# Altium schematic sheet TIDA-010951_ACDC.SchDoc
size 431 x 279 mm; Date: Not shown in title block; ApprovedBy: Not shown in title block; CheckedBy: Not shown in title block; Author: Not shown in title block; CompanyName: Not shown in title block; DrawnBy: Jenson Fang; Engineer: Not shown in title block; Organization: Not shown in title block; Address1: Not shown in title block; Address2: Not shown in title block; Address3: Not shown in title block; Address4: Not shown in title block; DocumentNumber: 1; Revision: Use project parameter SCH_Rev; SheetNumber: 1; SheetTotal: 2; PageSetup: Record=PageOptions¦CenterHorizontal=True¦CenterVertical=True¦PrintScale=1.00¦XCorrection=1.00¦YCorrection=1.00¦PrintKind=0¦BorderSize=5000000¦LeftOffset=0¦BottomOffset=0¦Orientation=2¦PaperLength=1000¦PaperWidth=1000¦Scale=100¦PaperSource=15¦PrintQuality=600¦MediaType=1¦DitherType=10¦PaperKind=Letter¦PrintScaleMode=1
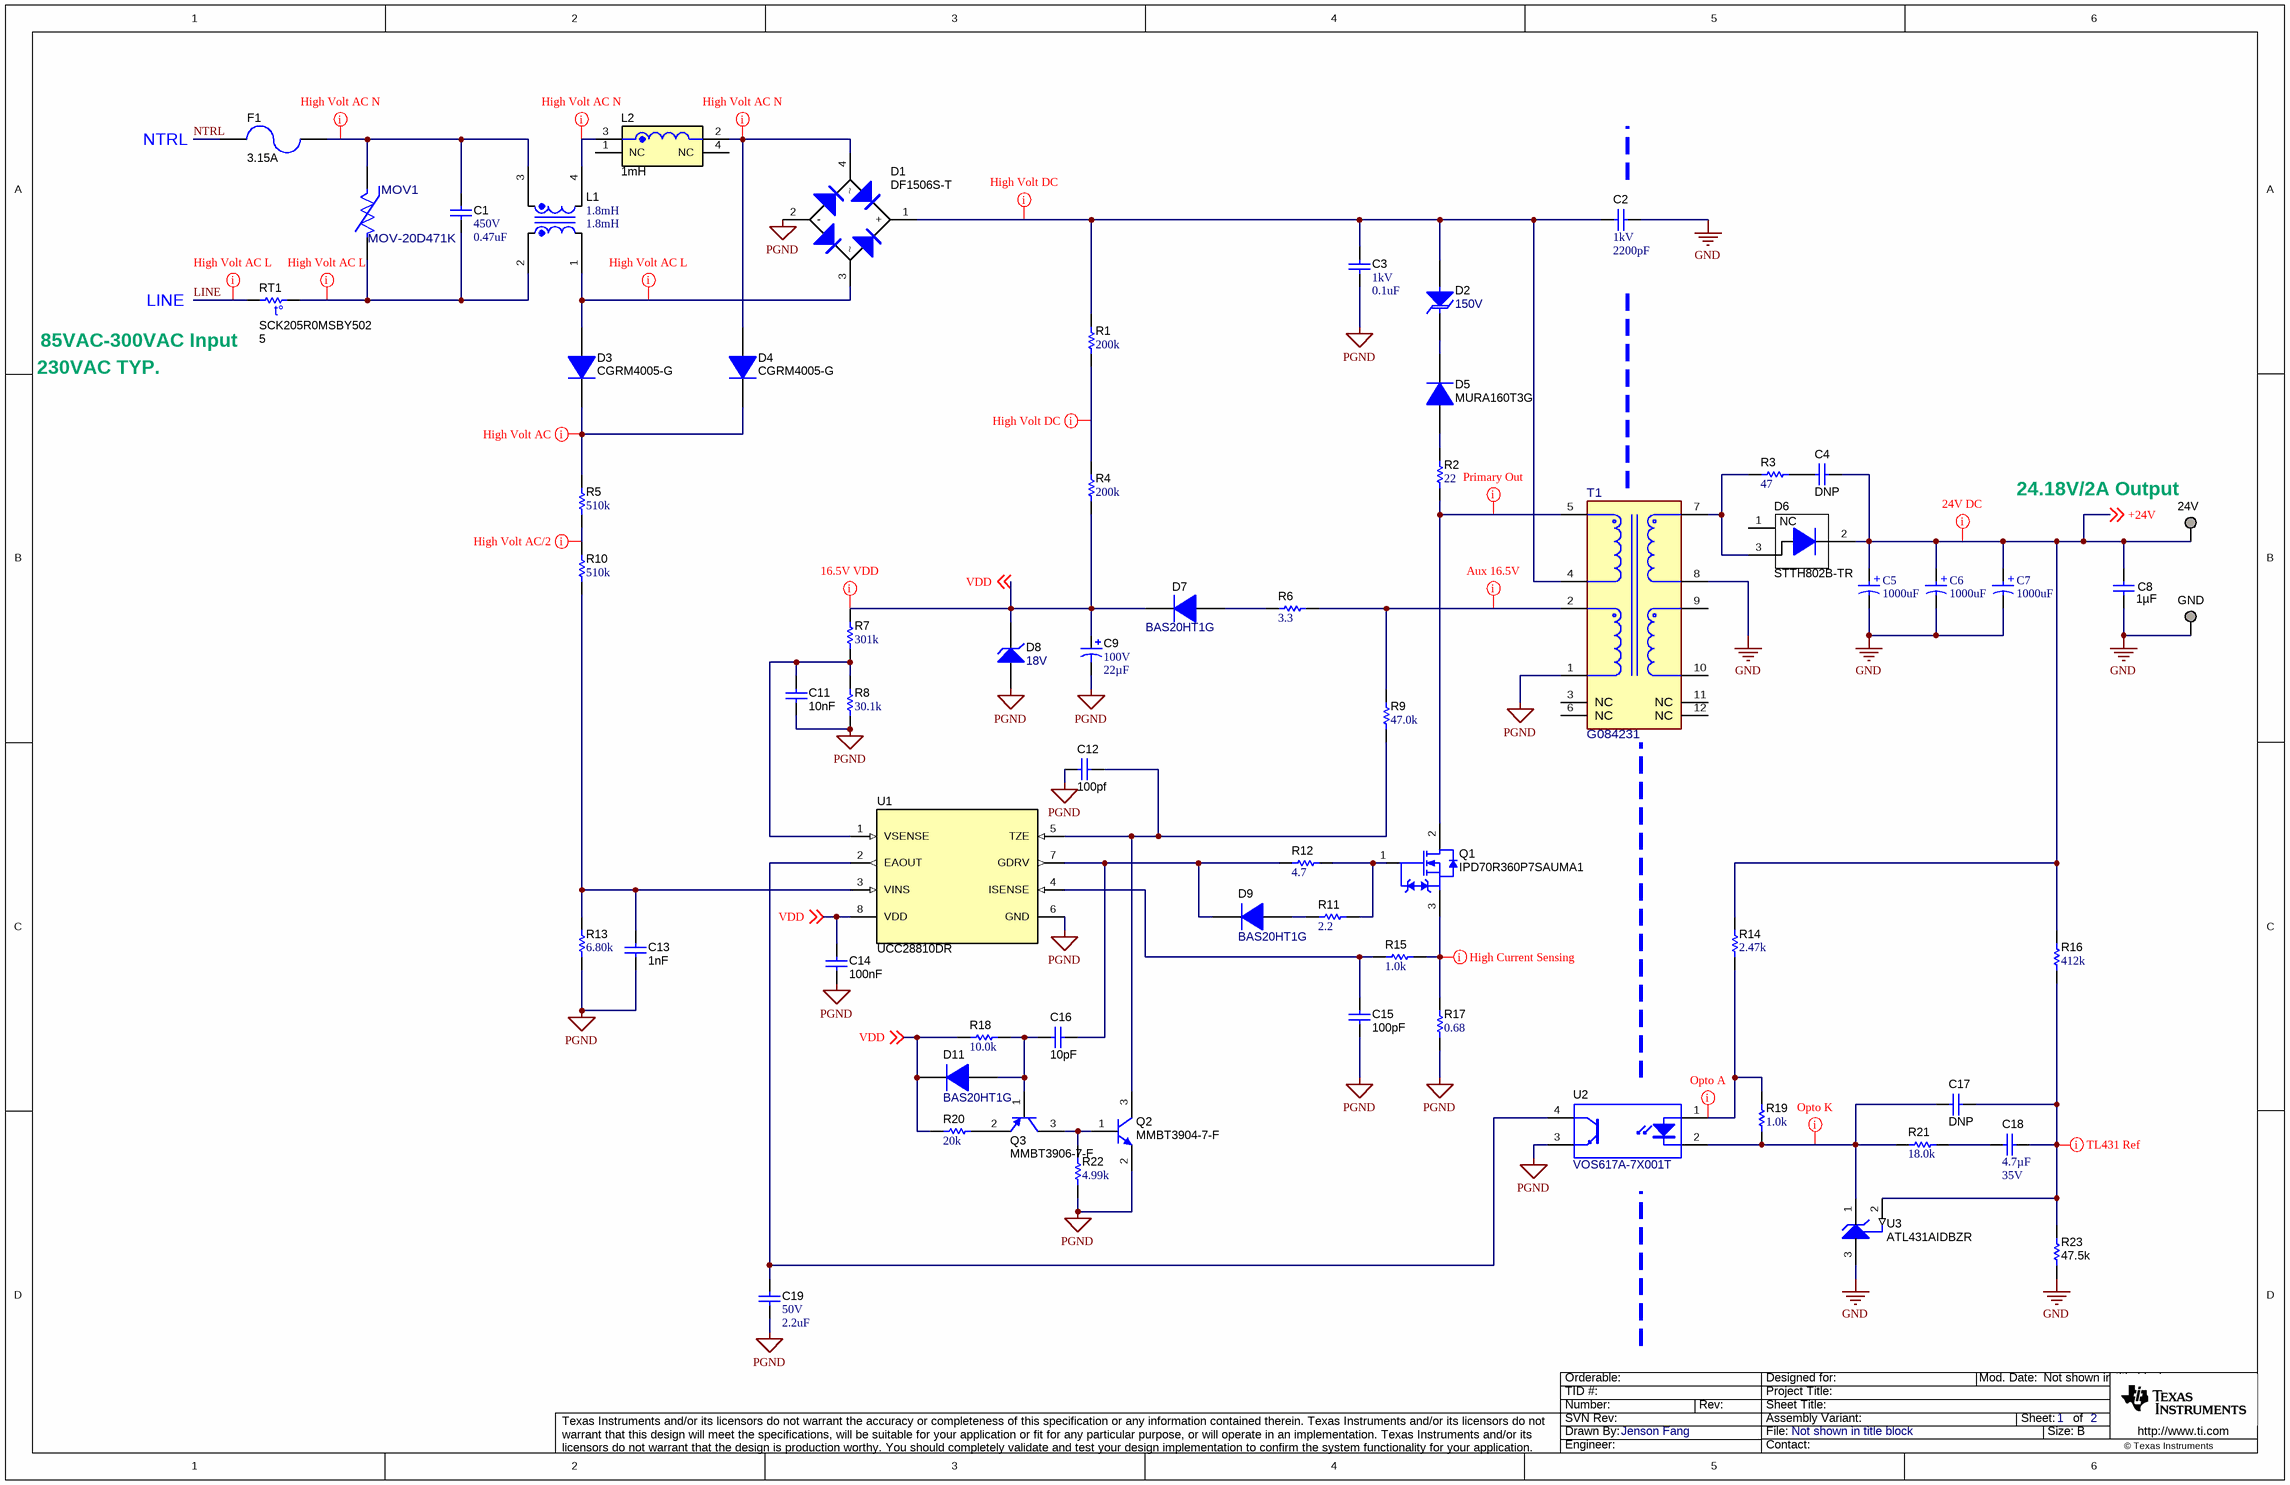
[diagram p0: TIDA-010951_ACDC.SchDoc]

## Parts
24V  TP_H0.45P0.75  [TP_H045P075]  (value not drawn)  (no BOM)
C1  VDC_V: 450V  ValueDisplayed: 0.47uF  [MPK_1800x650]  (hidden comment: 450MPK474J)
C2  VDC_V: 1kV  ValueDisplayed: 2200pF  [1206]  (hidden comment: GRM31BR73A222KW01L)
C3  VDC_V: 1kV  ValueDisplayed: 0.1uF  [2220]  (hidden comment: GRM55DR73A104KW01L)
C4  DNP  [0805_HV]
C5  1000uF  [WCAP-ATLL_D10H30]
C6  1000uF  [WCAP-ATLL_D10H30]
C7  1000uF  [WCAP-ATLL_D10H30]
C8  Cap_F: 1µF  [0603]  (hidden comment: UMK107AB7105KA-T)
C9  VDC_V: 100V  ValueDisplayed: 22µF  [VR_630X1100]  (hidden comment: UVR2A220MED1TD)
C11  Cap_F: 10nF  [0603]  (hidden comment: C1608X7R1H103K080AA)
C12  ValueDisplayed: 100pf  [0603]  (hidden comment: GRM1885C1H100JA01D)
C13  Cap_F: 1nF  [0603]  (hidden comment: C0603X102K5RACTU)
C14  Cap_F: 100nF  [0603]  (hidden comment: GRM188R71H104KA93D)
C15  ValueDisplayed: 100pF  [0603]  (hidden comment: C1608C0G1H101J080AE)
C16  ValueDisplayed: 10pF  [0603]  (hidden comment: GRM1885C1H100JA01D)
C17  ValueDisplayed: DNP  [0603]  (hidden comment: C1608X5R1V225K080AC)
C18  Cap_F: 4.7µF  VDC_V: 35V  [0805_HV]  (hidden comment: C2012X7R1V475K125AC)
C19  VDC_V: 50V  ValueDisplayed: 2.2uF  [0805_HV]  (hidden comment: C2012X6S1H225K125AB)
D1  DF1506S-T  [DF-S]
D2  value 150V  [SMC]  (hidden comment: SMCJ150A-TP)
D3  CGRM4005-G  [MINI-SMA]
D4  CGRM4005-G  [MINI-SMA]
D5  MURA160T3G  [SMA]
D6  STTH802B-TR  [DPAK]
D7  BAS20HT1G  [SOD-323]
D8  value 18V  [SOD-123]  (hidden comment: MMSZ4705-E3-08)
D9  BAS20HT1G  [SOD-323]
D11  BAS20HT1G  [SOD-323]
F1  value 3.15A  [FUSE_392]  (hidden comment: 39213150000)
GND  TP_H0.45P0.75  [TP_H045P075]  (value not drawn)  (no BOM)
L1  value 1.8mH  [WE-TFCH_UT]  (hidden comment: 744861018)
L2  value 1mH  [WE-TIF_1018]  (hidden comment: 7447231102)
MOV1  MOV-20D471K  [FP-MOV-20D471K_RADIAL-MFG]
Q1  IPD70R360P7SAUMA1  [DPAK]
Q2  MMBT3904-7-F  [SOT-23]
Q3  MMBT3906-7-F  [SOT-23]
R1  ValueDisplayed: 200k  [1210]  (hidden comment: RC1210JR-07200KL)
R2  ValueDisplayed: 22  [2512]  (hidden comment: CRCW251222R0JNEGHP)
R3  ValueDisplayed: 47  [1206]  (hidden comment: CRCW120647R0JNEA)
R4  ValueDisplayed: 200k  [1210]  (hidden comment: RC1210JR-07200KL)
R5  ValueDisplayed: 510k  [1206]  (hidden comment: RC1206FR-07510KL)
R6  ValueDisplayed: 3.3  [0805_HV]  (hidden comment: RC0805JR-073R3L)
R7  ValueDisplayed: 301k  [0603]  (hidden comment: RC0603FR-07301KL)
R8  ValueDisplayed: 30.1k  [0603]  (hidden comment: RC0603FR-0730K1L)
R9  ValueDisplayed: 47.0k  [0603]  (hidden comment: RC0603FR-0747KL)
R10  ValueDisplayed: 510k  [1206]  (hidden comment: RC1206FR-07510KL)
R11  ValueDisplayed: 2.2  [0805_HV]  (hidden comment: RC0805JR-072R2L)
R12  ValueDisplayed: 4.7  [0805_HV]  (hidden comment: RPC0805JT4R70)
R13  ValueDisplayed: 6.80k  [0603]  (hidden comment: RC0603FR-076K8L)
R14  ValueDisplayed: 2.47k  [0603]  (hidden comment: CR0603-JW-472GLF)
R15  ValueDisplayed: 1.0k  [0603]  (hidden comment: RC0603JR-071KL)
R16  ValueDisplayed: 412k  [0603]  (hidden comment: RC0603FR-07412KL)
R17  ValueDisplayed: 0.68  [2512]  (hidden comment: ERJ-1TRQJR68U)
R18  ValueDisplayed: 10.0k  [0402]  (hidden comment: ERJ-2RKF1002X)
R19  ValueDisplayed: 1.0k  [0603]  (hidden comment: RC0603JR-071KL)
R20  ValueDisplayed: 20k  [0402]  (hidden comment: ERJ-2GEJ203X)
R21  ValueDisplayed: 18.0k  [0603]  (hidden comment: RC0603FR-0718KL)
R22  ValueDisplayed: 4.99k  [0402]  (hidden comment: RC0402FR-074K99L)
R23  ValueDisplayed: 47.5k  [0603]  (hidden comment: RC0603FR-0747K5L)
RT1  SCK205R0MSBY502  value 5  [SCK20_S]
T1  G084231  [FP-G084231_PTH_TRANSFORMER_31MM50_24MM50-MFG]
U1  UCC28810DR  [D0008A_N]
U2  VOS617A-7X001T  [SSOP-4_VISHAY]
U3  ATL431AIDBZR  [DBZ0003A_N]

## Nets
GND: C2.1 C5.2(N) C6.2(N) C7.2(N) C8.2 GND.1 R23.1 T1.8 U3.3(ANODE)
PGND: C3.2 C9.2(-) C11.2 C12.1 C13.2 C14.2 C15.2 C19.2 D1.2(-) D8.2(A) Q2.2(E) R8.1 R13.1 R17.1 R22.1 T1.1 U1.6(GND) U2.3(E)
+24V: 24V.1 C4.2 C5.1(P) C6.1(P) C7.1(P) C8.1 D6.2(K) R14.2 R16.2 ; off-sheet +24V
LINE: RT1.1
NTRL: F1.2
VDD: C9.1(+) C14.1 D7.1(K) D8.1(K) D11.1(K) R4.1 R7.2 R18.1 R20.1 U1.8(VDD) ; off-sheet VDD
NetC1_1: C1.1 F1.1 L1.3 MOV1.2
NetC1_2: C1.2 L1.2 MOV1.1 RT1.2
NetC2_2: C2.2 C3.1 D1.1(+) D2.2(A) R1.2 T1.4
NetC4_1: C4.1 R3.2
NetC11_1: C11.1 R7.1 R8.2 U1.1(VSENSE)
NetC12_2: C12.2 Q2.3(C) R9.1 U1.5(TZE)
NetC13_1: C13.1 R10.1 R13.2 U1.3(VINS)
NetC15_1: C15.1 R15.2 U1.4(ISENSE)
NetC16_1: C16.1 D11.2(A) Q3.1(B) R18.2
NetC16_2: C16.2 D9.1(K) R12.1 U1.7(GDRV)
NetC17_1: C17.1 R19.1 R21.1 U2.2(K) U3.1(CATHODE)
NetC17_2: C17.2 C18.1 R16.1 R23.2 U3.2(REF)
NetC18_2: C18.2 R21.2
NetC19_1: C19.1 U1.2(EAOUT) U2.4(C)
NetD1_3: D1.3 D3.2(A) L1.1
NetD1_4: D1.4 D4.2(A) L2.2
NetD2_1: D2.1(K) D5.1(K)
NetD3_1: D3.1(K) D4.1(K) R5.2
NetD5_2: D5.2(A) R2.2
NetD6_3: D6.3(A) R3.1 T1.7
NetD7_2: D7.2(A) R6.1
NetD9_2: D9.2(A) R11.1
NetL1_4: L1.4 L2.3
NetQ1_1: Q1.1(G) R11.2 R12.2
NetQ1_2: Q1.2(D) R2.1 T1.5
NetQ1_3: Q1.3(S) R15.1 R17.2
NetQ2_1: Q2.1(B) Q3.3(C) R22.2
NetQ3_2: Q3.2(E) R20.2
NetR1_1: R1.1 R4.2
NetR5_1: R5.1 R10.2
NetR6_2: R6.2 R9.2 T1.2
NetR14_1: R14.1 R19.2 U2.1(A)

Not connected (* = marked no-connect by the designer): D6 1(NC); L2 1(NC) 4(NC); T1 3(NC) 6(NC) 9 10 11(NC) 12(NC)

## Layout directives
net class High Volt AC N: NetC1_1, NetD1_4, NetL1_4
net class High Volt AC L: LINE, NetC1_2, NetD1_3
net class High Volt DC: NetC2_2, NetR1_1
net class 18V VDD: VDD
net class Aux 16.5V: NetR6_2
net class Primary Out: NetQ1_2
net class 24V DC: +24V
net class TL431 Ref: NetC17_2
net class Opto K: NetC17_1
net class Opto A: NetR14_1
net class High Current Sensing: NetQ1_3
net class High Volt AC/2: NetR5_1
net class High Volt AC: NetD3_1

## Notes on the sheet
- NTRL
- LINE
- 230VAC TYP.
- (near RT1) 85VAC-300VAC Input
- (near 24V) 24.18V/2A Output

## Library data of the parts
24V GND = CMP-0003719-1: Testpoint; Manufacturer: Texas Instruments; CompType: Pad
C1 = CMP-0012309-3: CAP, Film, 0.47 uF, 450 V, +/- 5%, TH; Manufacturer: Rubycon; TaMin_C: -40°C; Polarized: N; Value1: Unknown; Value: 0.47uF; TaMax_C: 105°C; Cap_Case: 18x6.5mm; Cap_F: 470nF; AEC Category: Q200
C2 = CMP-0008918-2: CAP, CERM, 2200 pF, 1000 V, +/- 10%, X7R, 1206; Manufacturer: MuRata; TaMin_C: -55°C; Polarized: N; SizeAreaWB_mm2: 10.92; Value1: Unknown; U/M: EA; Value: 2200pF; TaMax_C: 125°C; SizeZ_mm: 1.35; SizeX_mm: 3.2; SizeY_mm: 1.6; Value2: 1000V; SizeArea_mm2: 5.12; Cap_F: 2.2nF; AEC Category: Q200
C3 = CMP-0009470-2: CAP, CERM, 0.1 uF, 1000 V, +/- 10%, X7R, 2220; Manufacturer: MuRata; TaMin_C: -55°C; Polarized: N; SizeAreaWB_mm2: 53.9; Value1: Unknown; U/M: EA; Value: 0.1uF; TaMax_C: 125°C; SizeZ_mm: 1.35; SizeX_mm: 5.7; SizeY_mm: 5; Value2: 1000V; SizeArea_mm2: 28.5; Cap_F: 100nF; AEC Category: Q200
C4 = CMP-0008310-1: TaMin_C: -55°C; Polarized: N; TempCo: X5R; SizeAreaWB_mm2: 6.75; Value1: Unknown; U/M: EA; TaMax_C: 85°C; Tolerance_%: 10%; SizeZ_mm: 1.45; SizeX_mm: 2; SizeY_mm: 1.25; Cap_Case: 0805; Value2: 250V; SizeArea_mm2: 2.5; AEC Category: Q200
C5 = CMP-03913-55434168-1: 860160575031 WCAP-ATLL Aluminum Electrolytic Capacitors 35VDC; Voltage Rating: 35V; Tolerance: 20%; Leakage Current: 350µA; Pitch: 5mm; Life (Hours): 6000hours; Impedance: 60mΩ; Capacitance: 1mF; Polarity: Polar; Material: Aluminium; Ripple Current: 2.136A
C6 C7 = CMP-03913-55434168-1: 860160575031 WCAP-ATLL Aluminum Electrolytic Capacitors; Voltage Rating: 35V; Tolerance: 20%; Leakage Current: 350µA; Pitch: 5mm; Life (Hours): 6000hours; Impedance: 60mΩ; Capacitance: 1mF; Polarity: Polar; Material: Aluminium; Ripple Current: 2.136A
C8 = CMP-0007508-5: CAP, CERM, 1 uF, 50 V, +/- 10%, X7R, 0603; Manufacturer: Taiyo Yuden; TaMin_C: -55°C; Polarized: N; SizeAreaWB_mm2: 4.68; Value1: Unknown; U/M: EA; Value: 1uF; TaMax_C: 125°C; SizeZ_mm: 1; SizeX_mm: 1.6; SizeY_mm: 0.8; Value2: 50V; SizeArea_mm2: 1.28; AEC Category: Q200
C9 = CMP-0860355-1: CAP, AL, 22 µF, 100 V, +/- 20%, TH; Manufacturer: Nichicon; TaMin_C: -40°C; SizeAreaWB_mm2: 68.89; AEC Category: Q200; AEC Qualified: N; U/M: EA; Cap_Case: 6.3x11mm; TaMax_C: 85°C; Value: 22uF; SizeY_mm: 6.3; CompType: Capacitor; Polarized: Y; SizeZ_mm: 12.5; SizeArea_mm2: 39.69
C11 = CMP-0007043-2: CAP, CERM, 0.01 uF, 50 V, +/- 10%, X7R, 0603; Manufacturer: TDK; TaMin_C: -55°C; ESR_ohm: 53.9m; Polarized: N; SizeAreaWB_mm2: 4.68; Value1: 0.0539 ohm; U/M: EA; Value: 0.01uF; TaMax_C: 125°C; SizeZ_mm: 1; SizeX_mm: 1.6; SizeY_mm: 0.8; Value2: 50V; SizeArea_mm2: 1.28; AEC Category: Q200
C12 C16 = CMP-0007170-4: CAP, CERM, 10 pF, 50 V, +/- 5%, C0G/NP0, 0603; Manufacturer: MuRata; TaMin_C: -55°C; Polarized: N; SizeAreaWB_mm2: 4.68; Value1: Unknown; U/M: EA; Value: 10pF; TaMax_C: 125°C; SizeZ_mm: 1; SizeX_mm: 1.6; SizeY_mm: 0.8; Value2: 50V; SizeArea_mm2: 1.28; AEC Category: Q200
C13 = CMP-0006976-5: CAP, CERM, 1000 pF, 50 V, +/- 10%, X7R, 0603; Manufacturer: Kemet; TaMin_C: -55°C; Polarized: N; SizeAreaWB_mm2: 4.68; Value1: Unknown; U/M: EA; Value: 1000pF; TaMax_C: 125°C; SizeZ_mm: 1; SizeX_mm: 1.6; SizeY_mm: 0.8; Value2: 50V; SizeArea_mm2: 1.28; AEC Category: Q200
C14 = CMP-0007434-4: CAP, CERM, 0.1 uF, 50 V, +/- 10%, X7R, 0603; Manufacturer: MuRata; TaMin_C: -55°C; Polarized: N; SizeAreaWB_mm2: 4.68; Value1: Unknown; U/M: EA; Value: 0.1uF; TaMax_C: 125°C; SizeZ_mm: 1; SizeX_mm: 1.6; SizeY_mm: 0.8; Value2: 50V; SizeArea_mm2: 1.28; AEC Category: Q200
C15 = CMP-0006989-1: CAP, CERM, 100 pF, 50 V, +/- 5%, C0G/NP0, 0603; Manufacturer: TDK; TaMin_C: -55°C; Polarized: N; SizeAreaWB_mm2: 4.68; Value1: Unknown; U/M: EA; Value: 100pF; TaMax_C: 125°C; SizeZ_mm: 1; SizeX_mm: 1.6; SizeY_mm: 0.8; Value2: 50V; SizeArea_mm2: 1.28; AEC Category: Q200
C17 = CMP-0007020-3: CAP, CERM, 2.2 uF, 35 V, +/- 10%, X5R, 0603; Manufacturer: TDK; TaMin_C: -55°C; ESR_ohm: 7.674m; Polarized: N; SizeAreaWB_mm2: 4.68; Value1: 0.007674 ohm; U/M: EA; Value: 2.2uF; TaMax_C: 85°C; SizeZ_mm: 1; SizeX_mm: 1.6; SizeY_mm: 0.8; Value2: 35V; SizeArea_mm2: 1.28; Cap_F: 2.2µF; IRMS_A: 1.8782A; AEC Category: Q200
C18 = CMP-0007885-2: CAP, CERM, 4.7 uF, 35 V, +/- 10%, X7R, 0805; Manufacturer: TDK; TaMin_C: -55°C; ESR_ohm: 2.346m; Polarized: N; SizeAreaWB_mm2: 6.75; Value1: 0.002346 ohm; U/M: EA; Value: 4.7uF; TaMax_C: 125°C; SizeZ_mm: 1.45; SizeX_mm: 2; SizeY_mm: 1.25; Cap_Case: 0805; SizeArea_mm2: 2.5; IRMS_A: 4.2602A; AEC Category: Q200
C19 = CMP-0007857-1: CAP, CERM, 2.2 uF, 50 V, +/- 10%, X6S, 0805; Manufacturer: TDK; TaMin_C: -55°C; ESR_ohm: 3.66m; Polarized: N; SizeAreaWB_mm2: 6.75; Value1: 0.00366 ohm; U/M: EA; Value: 2.2uF; TaMax_C: 105°C; SizeZ_mm: 1.45; SizeX_mm: 2; SizeY_mm: 1.25; Cap_Case: 0805; SizeArea_mm2: 2.5; Cap_F: 2.2µF; IRMS_A: 3.4121A; AEC Category: Q200
D1 = CMP-0029209-3: Diode, Switching-Bridge, 600 V, 1.5 A, DF-S; Manufacturer: Diodes Inc.; SizeAreaWB_mm2: 98.794; Value: 600V; SizeX_mm: 7.4; TJmax_C: 150°C; AEC Category: Q101; Value2: 1.1V; Green_REACh: Incomplete; Green_Lifecycle: Not Set; SizeArea_mm2: 62.974; SizeY_mm: 8.51; Value1: 1.5A; SizeZ_mm: 3.4
D2 = CMP-0005708-3: Diode, TVS, Uni, 150 V, 243 Vc, SMC; Manufacturer: Micro Commercial Components; SizeX_mm: 8.13; Vc: 243V; AEC Category: Q101; SizeY_mm: 6.22; SizeAreaWB_mm2: 83.2686; SizeZ_mm: 2.6; Ppk: 1.5kW; AEC Qualified: N; Ipp: 6.2A; Value1: 1500W; Vbr_Max: 185V; SizeArea_mm2: 50.5686; Vbr_Min: 167V
D3 D4 = CMP-0076945-2: Diode, P-N, 600 V, 1 A, MINI-SMA; Manufacturer: Comchip Technology; Green_Lifecycle: Not Set; Vr_V: 600V; Vf_V: 1.1V; SizeZ_mm: 1.7; SizeX_mm: 3.7; Value: 600V; SizeAreaWB_mm2: 12.22; AEC Qualified: N; SizeArea_mm2: 5.92; Io_A: 1A; TJmax_C: 150°C; AEC Category: Q101; SizeY_mm: 1.6; Green_REACh: Incomplete
D5 = CMP-0029033-2: Diode, Ultrafast, 600 V, 1 A, AEC-Q101, SMA; Manufacturer: ON Semiconductor; AEC Category: Q101; SizeX_mm: 5.59; Io_A: 1A; Green_Lifecycle: Active; Value2: 1.05V; SizeArea_mm2: 16.3228; SizeZ_mm: 2.87; TJmax_C: 175°C; Value: 600V; AEC Qualified: Y; SizeAreaWB_mm2: 37.3428; SizeY_mm: 2.92; Green_REACh: Passed
D6 = CMP-0079155-3: Diode, Ultrafast, 200 V, 8 A, DPAK; Manufacturer: STMicroelectronics; Vf_V: 1.05V; AEC Qualified: N; Value1: 8A; Value: 200V; SizeY_mm: 6.54; SizeAreaWB_mm2: 101.7114; SizeArea_mm2: 64.8114; SizeX_mm: 9.91; TJmax_C: 175°C; RJC_CperW: 3.2; SizeZ_mm: 2.29; AEC Category: Q101
D7 D9 D11 = CMP-0029150-1: Diode, Switching, 200 V, 0.2 A, AEC-Q101, SOD-323; Manufacturer: ON Semiconductor; Io_A: 200mA; Green_Lifecycle: Not Set; SizeAreaWB_mm2: 8.695; Vr_V: 200V; Green_REACh: Incomplete; Value1: 0.2A; TJmax_C: 150°C; U/M: EA; SizeZ_mm: 1; SizeX_mm: 2.7; SizeY_mm: 1.35; Vf_V: 1.25V; SizeArea_mm2: 3.645; AEC Qualified: Y; AEC Category: Q101
D8 = CMP-0077615-3: Diode, Zener, 18 V, 500 mW, SOD-123; Manufacturer: Vishay-Semiconductor; AEC Qualified: N; AEC Category: Q101; SizeX_mm: 3.85; SizeY_mm: 1.7; SizeZ_mm: 1.35; Value1: 0.5W; SizeArea_mm2: 6.545; SizeAreaWB_mm2: 13.095; Power_W: 500mW; RJA_CperW: 340
F1 = CMP-0003561-2: Fuse, 3.15 A, 250VAC/VDC, TH; Manufacturer: Littelfuse; VAC_V: 250V
L1 = CMP-0076855-1: Coupled inductor, 1.8 mH, 1 A, 0.31 ohm, TH; Manufacturer: Wurth Elektronik; AEC Category: Q200; DCR_ohm: 3.1d
L2 = CMP-0079596-1: Inductor, Wirewound, 1 mH, 0.8 A, 0.75 ohm, TH; Manufacturer: Wurth Elektronik; SizeAreaWB_mm2: 169; Irms: 0.8A @ 40C rise; SizeArea_mm2: 121; AEC Qualified: N; AEC Category: Q200; SizeZ_mm: 19; Imax_A: 1A; SizeY_mm: 11; Value2: 0.8A; Isat: 1A @ 10% inductance drop; DCR_ohm: 8.5
MOV1 = CMP-0092775-1: 470 V 6.5 kA Varistor 1 Circuit Through Hole Disc 20mm; Manufacturer: Bourns Inc.; ValueDisplayed: 1020pF; AEC Qualified: No; Clamping Voltage: 775V; Vc: 100A; SizeZ_mm: 26mm; Varistor Voltage: 423V; Voltage Tolerance: 10%; VDC_V: 385V
Q1 = CMP-0081521-2: MOSFET, N-CH, 700 V, 12.5 A, DPAK; Alternate Manufacturer: None; Manufacturer: Infineon Technologies; ChType: N; Value1: ? ohm; ChMode: Enhancement; Value: 700V; SizeArea_mm2: 64.8114; IdsMax_A: 12.5A; Value2: 16.4 nC; SizeX_mm: 9.91; QgTyp_nC: 16.4; AEC Category: Q101; Vgs_V: 16V; SizeZ_mm: 2.29; SizeAreaWB_mm2: 101.7114; SizeY_mm: 6.54
Q2 = CMP-0000387-2: Transistor, NPN, 40 V, 0.2 A, SOT-23; Manufacturer: Diodes Inc.; TaMax_C: 150°C; Value2: 400; Value1: 0.2 A; Vcesat1_V: 2dV; SizeX_mm: 2.5; SizeY_mm: 3; TaMin_C: -55°C; IcRated_A: 2dA; CompType: BJT; SizeZ_mm: 1.1; Value: 40 V; SizeArea_mm2: 7.5; NPN: 1; Vceo_V: 40V; PNP: 0; AEC Category: Q101; SizeAreaWB_mm2: 14; U/M: EA
Q3 = CMP-0000326-2: Transistor, PNP, 40 V, 0.2 A, SOT-23; Manufacturer: Diodes Inc.; TaMax_C: 150°C; Value2: 400; Value1: 0.2 A; Vcesat1_V: 2.5dV; SizeX_mm: 2.5; SizeY_mm: 3; TaMin_C: -55°C; IcRated_A: 2dA; CompType: BJT; SizeZ_mm: 1.1; Value: 40 V; SizeArea_mm2: 7.5; NPN: 0; Vceo_V: 40V; PNP: 1; AEC Category: Q101; SizeAreaWB_mm2: 14; U/M: EA
R1 R4 = CMP-0083494-1: RES, 200 k, 5%, 0.5 W, 1210; Manufacturer: Yageo; Power_W: 500mW; TempCo: 100 ppm/C; SizeAreaWB_mm2: 14.7; Value: 200k; EIA_Code: E24; SizeX_mm: 3.2; SizeY_mm: 2.5; SizeZ_mm: 1.35; Value2: 0.5W; SizeArea_mm2: 8; AEC Qualified: N; VDC_V: 200V; AEC Category: Q200
R2 = CMP-0015919-3: RES, 22, 5%, 1.5 W, AEC-Q200 Grade 0, 2512; Manufacturer: Vishay-Dale; Power_W: 1.5W; TempCo: 200 ppm/C; Value_Code: 22R0; Value: 22; EIA_Code: E24; SizeX_mm: 6.3; SizeY_mm: 3.2; SizeZ_mm: 0.71; SizeArea_mm2: 20.16; AEC Qualified: Y; VDC_V: 500V; AEC Category: Q200; AEC Grade: 0
R3 = CMP-0018687-3: RES, 47, 5%, 0.25 W, AEC-Q200 Grade 0, 1206; Manufacturer: Vishay-Dale; Power_W: 250mW; TempCo: 200 ppm/C; Value_Code: 47R0; Value: 47; EIA_Code: E24; SizeX_mm: 3.2; SizeY_mm: 1.6; SizeZ_mm: 1.35; Value2: 0.25W; SizeArea_mm2: 5.12; AEC Qualified: Y; VDC_V: 200V; AEC Category: Q200; AEC Grade: 0
R5 R10 = CMP-0018353-2: RES, 510 k, 1%, 0.25 W, 1206; Manufacturer: Yageo America; Power_W: 250mW; TempCo: 100 ppm/C; U/M: EA; Value: 510k; SizeX_mm: 3.2; SizeY_mm: 1.6; SizeZ_mm: 1.35; Value2: 0.25W; SizeArea_mm2: 5.12; VDC_V: 200V; AEC Category: Q200
R6 = CMP-0020817-2: RES, 3.3, 5%, 0.125 W, 0805; Manufacturer: Yageo America; Power_W: 125mW; TempCo: 200 ppm/C; Value_Code: 3R30; U/M: EA; Value: 3.3; EIA_Code: E24; SizeX_mm: 2; SizeY_mm: 1.25; SizeZ_mm: 1.45; Value2: 0.125W; SizeArea_mm2: 2.5; VDC_V: 150V; AEC Category: Q200
R7 = CMP-0023014-4: RES, 301 k, 1%, 0.1 W, 0603; Manufacturer: Yageo; Power_W: 100mW; TempCo: 100 ppm/C; Value: 301k; EIA_Code: E96; SizeX_mm: 1.6; SizeY_mm: 0.8; SizeZ_mm: 1; Value2: 0.1W; SizeArea_mm2: 1.28; AEC Qualified: N; VDC_V: 75V; AEC Category: Q200; SizeAreaWB_mm2: 4.68
R8 = CMP-0023018-5: RES, 30.1 k, 1%, 0.1 W, 0603; Manufacturer: Yageo; Power_W: 100mW; TempCo: 100 ppm/C; Value_Code: 30k1; Value: 30.1k; EIA_Code: E96; SizeX_mm: 1.6; SizeY_mm: 0.8; SizeZ_mm: 1; Value2: 0.1W; SizeArea_mm2: 1.28; AEC Qualified: N; VDC_V: 75V; AEC Category: Q200; SizeAreaWB_mm2: 4.68
R9 = CMP-0023133-5: RES, 47.0 k, 1%, 0.1 W, 0603; Manufacturer: Yageo; Power_W: 100mW; TempCo: 100 ppm/C; Value_Code: 47k0; Value: 47.0k; Res_ohm: 47k; SizeX_mm: 1.6; SizeY_mm: 0.8; SizeZ_mm: 1; Value2: 0.1W; SizeArea_mm2: 1.28; AEC Qualified: N; VDC_V: 75V; AEC Category: Q200; SizeAreaWB_mm2: 4.68
R11 = CMP-0020812-2: RES, 2.2, 5%, 0.125 W, 0805; Manufacturer: Yageo America; Power_W: 125mW; TempCo: 200 ppm/C; Value_Code: 2R20; U/M: EA; Value: 2.2; EIA_Code: E24; SizeX_mm: 2; SizeY_mm: 1.25; SizeZ_mm: 1.45; Value2: 0.125W; SizeArea_mm2: 2.5; VDC_V: 150V; AEC Category: Q200
R12 = CMP-0020832-2: RES, 4.7, 5%, 0.25 W, 0805; Manufacturer: Stackpole Electronics Inc; Power_W: 250mW; TempCo: 200 ppm/C; Value_Code: 4R70; U/M: EA; Value: 4.7; EIA_Code: E24; SizeX_mm: 2; SizeY_mm: 1.25; SizeZ_mm: 1.45; Value2: 0.25W; SizeArea_mm2: 2.5; AEC Qualified: N; AEC Category: Q200
R13 = CMP-0023253-5: RES, 6.80 k, 1%, 0.1 W, 0603; Manufacturer: Yageo; Power_W: 100mW; TempCo: 100 ppm/C; Value_Code: 6k80; Value: 6.80k; Res_ohm: 6.8k; SizeX_mm: 1.6; SizeY_mm: 0.8; SizeZ_mm: 1; Value2: 0.1W; SizeArea_mm2: 1.28; AEC Qualified: N; VDC_V: 75V; AEC Category: Q200; SizeAreaWB_mm2: 4.68
R14 = CMP-0025696-3: RES, 4.7 k, 5%, 0.1 W, 0603; Manufacturer: Bourns; Power_W: 100mW; TempCo: 200 ppm/C; Value_Code: 4k70; U/M: EA; Value: 4.7k; EIA_Code: E24; SizeX_mm: 1.6; SizeY_mm: 0.8; SizeZ_mm: 1; Value2: 0.1W; SizeArea_mm2: 1.28; AEC Qualified: N; VDC_V: 50V; AEC Category: Q200
R15 R19 = CMP-0025899-5: RES, 1.0 k, 5%, 0.1 W, 0603; Manufacturer: Yageo; Power_W: 100mW; TempCo: 100 ppm/C; Value_Code: 1k00; Value: 1.0k; EIA_Code: E24; Res_ohm: 1k; SizeX_mm: 1.6; SizeY_mm: 0.8; SizeZ_mm: 1; Value2: 0.1W; SizeArea_mm2: 1.28; AEC Qualified: N; VDC_V: 75V; AEC Category: Q200; SizeAreaWB_mm2: 4.68
R16 = CMP-0023100-4: RES, 412 k, 1%, 0.1 W, 0603; Manufacturer: Yageo; Power_W: 100mW; TempCo: 100 ppm/C; Value: 412k; EIA_Code: E96; SizeX_mm: 1.6; SizeY_mm: 0.8; SizeZ_mm: 1; Value2: 0.1W; SizeArea_mm2: 1.28; AEC Qualified: N; VDC_V: 75V; AEC Category: Q200; SizeAreaWB_mm2: 4.68
R17 = CMP-0016021-2: RES, 0.68, 5%, 1 W, 2512; Manufacturer: Panasonic; Power_W: 1W; TempCo: 200 ppm/C; Value_Code: R680; U/M: EA; Value: 0.68; SizeX_mm: 6.3; SizeY_mm: 3.2; SizeZ_mm: 0.71; SizeArea_mm2: 20.16; AEC Category: Q200
R18 = CMP-0026658-1: RES, 10.0 k, 1%, 0.1 W, 0402; Manufacturer: Panasonic; Power_W: 100mW; TempCo: 100 ppm/C; Value_Code: 10k0; U/M: EA; Value: 10.0k; EIA_Code: E96; Res_ohm: 10k; SizeX_mm: 1; SizeY_mm: 0.5; SizeZ_mm: 0.6; Value2: 0.1W; VDC_V: 50V; AEC Category: Q200
R20 = CMP-0026996-2: RES, 20 k, 5%, 0.1 W, AEC-Q200 Grade 0, 0402; Manufacturer: Panasonic; Power_W: 100mW; TempCo: 200 ppm/C; Value_Code: 20k0; U/M: EA; Value: 20k; EIA_Code: E24; SizeX_mm: 1; SizeY_mm: 0.5; SizeZ_mm: 0.6; Value2: 0.1W; AEC Qualified: Y; VDC_V: 50V; AEC Grade: 0; AEC Category: Q200
R21 = CMP-0022852-5: RES, 18.0 k, 1%, 0.1 W, 0603; Manufacturer: Yageo; Power_W: 100mW; TempCo: 100 ppm/C; Value_Code: 18k0; Value: 18.0k; Res_ohm: 18k; SizeX_mm: 1.6; SizeY_mm: 0.8; SizeZ_mm: 1; Value2: 0.1W; SizeArea_mm2: 1.28; AEC Qualified: N; VDC_V: 75V; AEC Category: Q200; SizeAreaWB_mm2: 4.68
R22 = CMP-0026740-1: RES, 4.99 k, 1%, 0.063 W, 0402; Manufacturer: Yageo America; Power_W: 63mW; TempCo: 100 ppm/C; Value_Code: 4k99; U/M: EA; Value: 4.99k; EIA_Code: E96; SizeX_mm: 1; SizeY_mm: 0.5; SizeZ_mm: 0.6; Value2: 0.063W; AEC Qualified: N; VDC_V: 50V; AEC Category: Q200
R23 = CMP-0023132-5: RES, 47.5 k, 1%, 0.1 W, 0603; Manufacturer: Yageo; Power_W: 100mW; TempCo: 100 ppm/C; Value_Code: 47k5; Value: 47.5k; EIA_Code: E96; SizeX_mm: 1.6; SizeY_mm: 0.8; SizeZ_mm: 1; Value2: 0.1W; SizeArea_mm2: 1.28; AEC Qualified: N; VDC_V: 75V; AEC Category: Q200; SizeAreaWB_mm2: 4.68
RT1 = CMP-0078760-1: Thermistor NTC, 5 ohm, 20%, D20xT6mm; Manufacturer: TKS; SizeAreaWB_mm2: 176; SizeArea_mm2: 120; TaMax_C: 200°C; SizeZ_mm: 24.5; TaMin_C: -40°C; Power_W: 4.9W; SizeY_mm: 20; U/M: EA; SizeX_mm: 6
T1 = CMP-0098488-1: FLYBACK TRANSFORMER; Manufacturer: GCI Technologies; DCR_ohm: 0.7; Ind_H: 470µH; Ns1toNp: 1:0.1746/1:0.254/1:0.0635; Rsec1_ohm: 45m; SizeZ_mm: 30mm; AEC Qualified: No; Voltage_Isolation_Vrms: 3kV
U1 = CMP-0029884-1: LED Lighting Power Controller, -40 to +105 degC, 8-pin SOIC (D), Green (RoHS & no Sb/Br); Manufacturer: Texas Instruments; Rating: Catalog; Frequency(Max)(kHz): 200
U2 = CMP-0006163-3: Optocoupler, 3.75 kV, 80-160% CTR, SMT; Manufacturer: Vishay-Semiconductor; CTR (Max): 160%; CTR (Min): 80%; Voltage_Isolation_Vrms: 3.75kV
U3 = CMP-0066199-1: 2.5V Low Iq Adjustable Precision Shunt Regulator, DBZ0003A (SOT-23-3); Alternate Manufacturer: Texas Instruments; SizeAreaWB_mm2: 14.0; U/M: EA; SizeZ_mm: 1.12; SizeX_mm: 2.5; SizeY_mm: 3.0; SizeArea_mm2: 7.5; CompType: IC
